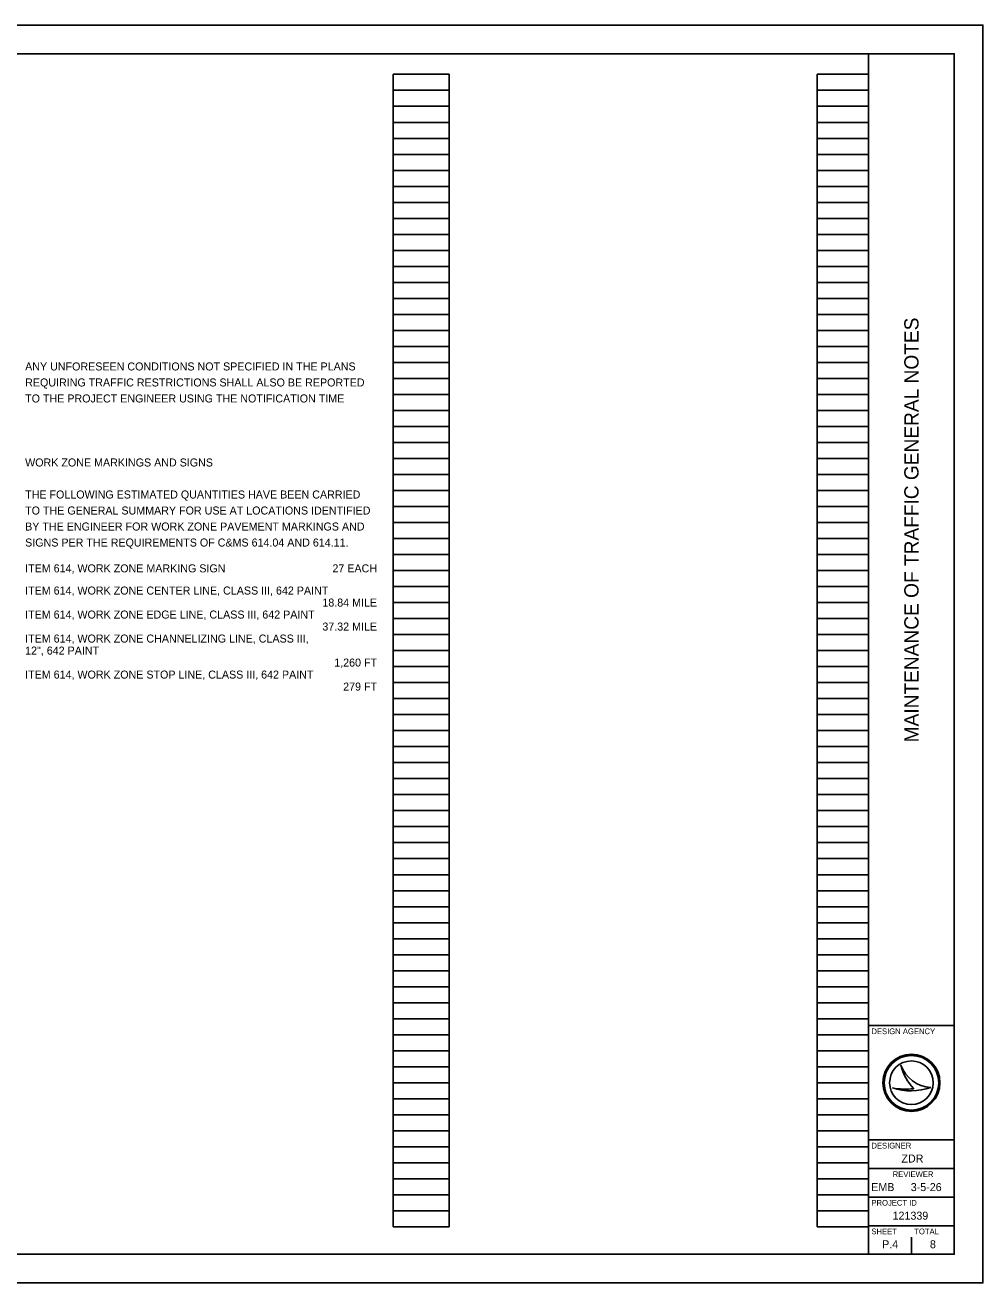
# Model space of a CAD drawing. Extents: x 0 to 34, y 0 to 22.
# Drawn here: x 17.24 to 34, y 0 to 22 of the extents above; entities that cross this region are included whole.
import ezdxf

# ---------------------------------------------------------------- set-up
doc = ezdxf.new("R2010")
doc.units = 0
for name, color, linetype in [('SH_Border', 7, 'Continuous'), ('SH_Cut_Line', 7, 'Continuous'), ('SH_Data', 7, 'Continuous'), ('SH_Text', 7, 'Continuous')]:
    doc.layers.add(name, color=color, linetype=linetype)

msp = doc.modelspace()

# ---------------------------------------------------------------- linework, layer by layer
at = {"layer": 'SH_Border'}
for p, q in [((32, 0.5), (32, 21.5)), ((32, 4.5), (33.5, 4.5)), ((32, 2.5), (33.5, 2.5)), ((32, 2), (33.5, 2)), ((32, 1.5), (33.5, 1.5)), ((32, 1), (33.5, 1))]:
    msp.add_line(p, q, dxfattribs=at)
msp.add_lwpolyline([(1.5, 21.5), (33.5, 21.5), (33.5, 0.5), (1.5, 0.5)], close=True, dxfattribs=at)
at = {"layer": 'SH_Cut_Line'}
msp.add_lwpolyline([(0, 0), (34, 0), (34, 22), (0, 22)], close=True, dxfattribs=at)
at = {"layer": 'SH_Data'}
for p, q in [((23.68, 0.98), (23.68, 21.14)), ((23.68, 21.14), (24.66, 21.14)), ((24.66, 0.98), (24.66, 21.14)), ((31.1, 0.98), (31.1, 21.14)), ((31.1, 21.14), (32, 21.14)), ((32, 0.98), (32, 21.14)), ((23.68, 20.86), (24.66, 20.86)), ((31.1, 20.86), (32, 20.86)), ((23.68, 20.58), (24.66, 20.58)), ((31.1, 20.58), (32, 20.58)), ((23.68, 20.3), (24.66, 20.3)), ((31.1, 20.3), (32, 20.3)), ((23.68, 20.02), (24.66, 20.02)), ((31.1, 20.02), (32, 20.02)), ((23.68, 19.74), (24.66, 19.74)), ((31.1, 19.74), (32, 19.74)), ((23.68, 19.46), (24.66, 19.46)), ((31.1, 19.46), (32, 19.46)), ((23.68, 19.18), (24.66, 19.18)), ((31.1, 19.18), (32, 19.18)), ((23.68, 18.9), (24.66, 18.9)), ((31.1, 18.9), (32, 18.9)), ((23.68, 18.62), (24.66, 18.62)), ((31.1, 18.62), (32, 18.62)), ((23.68, 18.34), (24.66, 18.34)), ((31.1, 18.34), (32, 18.34)), ((23.68, 18.06), (24.66, 18.06)), ((31.1, 18.06), (32, 18.06)), ((23.68, 17.78), (24.66, 17.78)), ((31.1, 17.78), (32, 17.78)), ((23.68, 17.5), (24.66, 17.5)), ((31.1, 17.5), (32, 17.5)), ((23.68, 17.22), (24.66, 17.22)), ((31.1, 17.22), (32, 17.22)), ((23.68, 16.94), (24.66, 16.94)), ((31.1, 16.94), (32, 16.94)), ((23.68, 16.66), (24.66, 16.66)), ((31.1, 16.66), (32, 16.66)), ((23.68, 16.38), (24.66, 16.38)), ((31.1, 16.38), (32, 16.38)), ((23.68, 16.1), (24.66, 16.1)), ((31.1, 16.1), (32, 16.1)), ((23.68, 15.82), (24.66, 15.82)), ((31.1, 15.82), (32, 15.82)), ((23.68, 15.54), (24.66, 15.54)), ((31.1, 15.54), (32, 15.54)), ((23.68, 15.26), (24.66, 15.26)), ((31.1, 15.26), (32, 15.26)), ((23.68, 14.98), (24.66, 14.98)), ((31.1, 14.98), (32, 14.98)), ((23.68, 14.7), (24.66, 14.7)), ((31.1, 14.7), (32, 14.7)), ((23.68, 14.42), (24.66, 14.42)), ((31.1, 14.42), (32, 14.42)), ((23.68, 14.14), (24.66, 14.14)), ((31.1, 14.14), (32, 14.14)), ((23.68, 13.86), (24.66, 13.86)), ((31.1, 13.86), (32, 13.86)), ((23.68, 13.58), (24.66, 13.58)), ((31.1, 13.58), (32, 13.58)), ((23.68, 13.3), (24.66, 13.3)), ((31.1, 13.3), (32, 13.3)), ((23.68, 13.02), (24.66, 13.02)), ((31.1, 13.02), (32, 13.02)), ((23.68, 12.74), (24.66, 12.74)), ((31.1, 12.74), (32, 12.74)), ((23.68, 12.46), (24.66, 12.46)), ((31.1, 12.46), (32, 12.46)), ((23.68, 12.18), (24.66, 12.18)), ((31.1, 12.18), (32, 12.18)), ((23.68, 11.9), (24.66, 11.9)), ((31.1, 11.9), (32, 11.9)), ((23.68, 11.62), (24.66, 11.62)), ((31.1, 11.62), (32, 11.62)), ((23.68, 11.34), (24.66, 11.34)), ((31.1, 11.34), (32, 11.34)), ((23.68, 11.06), (24.66, 11.06)), ((31.1, 11.06), (32, 11.06)), ((23.68, 10.78), (24.66, 10.78)), ((31.1, 10.78), (32, 10.78)), ((23.68, 10.5), (24.66, 10.5)), ((31.1, 10.5), (32, 10.5)), ((23.68, 10.22), (24.66, 10.22)), ((31.1, 10.22), (32, 10.22)), ((23.68, 9.94), (24.66, 9.94)), ((31.1, 9.94), (32, 9.94)), ((23.68, 9.66), (24.66, 9.66)), ((31.1, 9.66), (32, 9.66)), ((23.68, 9.38), (24.66, 9.38)), ((31.1, 9.38), (32, 9.38)), ((23.68, 9.1), (24.66, 9.1)), ((31.1, 9.1), (32, 9.1)), ((23.68, 8.82), (24.66, 8.82)), ((31.1, 8.82), (32, 8.82)), ((23.68, 8.54), (24.66, 8.54)), ((31.1, 8.54), (32, 8.54)), ((23.68, 8.26), (24.66, 8.26)), ((31.1, 8.26), (32, 8.26)), ((23.68, 7.98), (24.66, 7.98)), ((31.1, 7.98), (32, 7.98)), ((23.68, 7.7), (24.66, 7.7)), ((31.1, 7.7), (32, 7.7)), ((23.68, 7.42), (24.66, 7.42)), ((31.1, 7.42), (32, 7.42)), ((23.68, 7.14), (24.66, 7.14)), ((31.1, 7.14), (32, 7.14)), ((23.68, 6.86), (24.66, 6.86)), ((31.1, 6.86), (32, 6.86)), ((23.68, 6.58), (24.66, 6.58)), ((31.1, 6.58), (32, 6.58)), ((23.68, 6.3), (24.66, 6.3)), ((31.1, 6.3), (32, 6.3)), ((23.68, 6.02), (24.66, 6.02)), ((31.1, 6.02), (32, 6.02)), ((23.68, 5.74), (24.66, 5.74)), ((31.1, 5.74), (32, 5.74)), ((23.68, 5.46), (24.66, 5.46)), ((31.1, 5.46), (32, 5.46)), ((23.68, 5.18), (24.66, 5.18)), ((31.1, 5.18), (32, 5.18)), ((23.68, 4.9), (24.66, 4.9)), ((31.1, 4.9), (32, 4.9)), ((23.68, 4.62), (24.66, 4.62)), ((31.1, 4.62), (32, 4.62)), ((23.68, 4.34), (24.66, 4.34)), ((31.1, 4.34), (32, 4.34)), ((23.68, 4.06), (24.66, 4.06)), ((31.1, 4.06), (32, 4.06)), ((23.68, 3.78), (24.66, 3.78)), ((31.1, 3.78), (32, 3.78)), ((32.567, 3.81), (32.567, 3.81)), ((23.68, 3.5), (24.66, 3.5)), ((31.1, 3.5), (32, 3.5)), ((32.417, 3.41), (32.417, 3.41)), ((32.75, 3.5), (32.75, 3.5)), ((33.087, 3.419), (33.087, 3.419)), ((23.68, 3.22), (24.66, 3.22)), ((31.1, 3.22), (32, 3.22)), ((23.68, 2.94), (24.66, 2.94)), ((31.1, 2.94), (32, 2.94)), ((23.68, 2.66), (24.66, 2.66)), ((31.1, 2.66), (32, 2.66)), ((23.68, 2.38), (24.66, 2.38)), ((31.1, 2.38), (32, 2.38)), ((23.68, 2.1), (24.66, 2.1)), ((31.1, 2.1), (32, 2.1)), ((23.68, 1.82), (24.66, 1.82)), ((31.1, 1.82), (32, 1.82)), ((23.68, 1.54), (24.66, 1.54)), ((31.1, 1.54), (32, 1.54)), ((23.68, 1.26), (24.66, 1.26)), ((31.1, 1.26), (32, 1.26)), ((23.68, 0.98), (24.66, 0.98)), ((31.1, 0.98), (32, 0.98)), ((32.375, 0.675), (32.375, 0.675)), ((32.75, 0.5), (32.75, 0.8))]:
    msp.add_line(p, q, dxfattribs=at)
for radius in [0.5, 0.477, 0.477, 0.382]:
    msp.add_circle((32.75, 3.5), radius, dxfattribs=at)
for centre, radius, start, end in [((33.116, 3.998), 0.58, 198.9257, 198.9319), ((33.347, 3.97), 0.796, 191.6379, 191.6421), ((33.116, 3.998), 0.58, 198.9319, 267.1657), ((33.347, 3.97), 0.796, 191.6421, 226.0947), ((32.739, 4.37), 1.013, 251.4576, 290.0832), ((32.648, 4.654), 1.266, 259.4964, 259.4995), ((32.739, 4.37), 1.013, 251.4527, 251.4576), ((32.648, 4.654), 1.266, 259.4995, 276.6672)]:
    msp.add_arc(centre, radius, start, end, dxfattribs=at)

# ---------------------------------------------------------------- texts
msp.add_text('MAINTENANCE OF TRAFFIC GENERAL NOTES', height=0.25, rotation=90, dxfattribs=at).set_placement((32.875, 9.455))
for s, height, p in [('DESIGN AGENCY', 0.1, (32.05, 4.35)), ('DESIGNER', 0.1, (32.05, 2.35)), ('ZDR', 0.14, (32.575, 2.105)), ('REVIEWER', 0.1, (32.422, 1.85)), ('EMB', 0.14, (32.047, 1.605)), ('3-5-26', 0.14, (32.738, 1.605)), ('PROJECT ID', 0.1, (32.05, 1.35)), ('121339', 0.14, (32.42, 1.105)), ('SHEET', 0.1, (32.05, 0.85)), ('TOTAL', 0.1, (32.8, 0.85)), ('P.4', 0.14, (32.237, 0.605)), ('8', 0.14, (33.074, 0.605))]:
    msp.add_text(s, height=height, dxfattribs=at).set_placement(p)
at = {"layer": 'SH_Text'}
for s, p in [('ANY UNFORESEEN CONDITIONS NOT SPECIFIED IN THE PLANS', (17.24, 15.96)), ('REQUIRING TRAFFIC RESTRICTIONS SHALL ALSO BE REPORTED', (17.24, 15.68)), ('TO THE PROJECT ENGINEER USING THE NOTIFICATION TIME', (17.24, 15.4)), ('WORK ZONE MARKINGS AND SIGNS', (17.24, 14.28)), ('THE FOLLOWING ESTIMATED QUANTITIES HAVE BEEN CARRIED', (17.24, 13.72)), ('TO THE GENERAL SUMMARY FOR USE AT LOCATIONS IDENTIFIED', (17.24, 13.44)), ('BY THE ENGINEER FOR WORK ZONE PAVEMENT MARKINGS AND', (17.24, 13.16)), ('SIGNS PER THE REQUIREMENTS OF C&MS 614.04 AND 614.11.', (17.24, 12.88)), ('ITEM 614, WORK ZONE MARKING SIGN                                    27 EACH', (17.24, 12.428)), ('ITEM 614, WORK ZONE CENTER LINE, CLASS III, 642 PAINT', (17.24, 12.04)), ('                                                                                                    18.84 MILE', (17.24, 11.83)), ('ITEM 614, WORK ZONE EDGE LINE, CLASS III, 642 PAINT', (17.24, 11.62)), ('                                                                                                    37.32 MILE', (17.24, 11.41)), ('ITEM 614, WORK ZONE CHANNELIZING LINE, CLASS III, ', (17.24, 11.2)), ('12", 642 PAINT', (17.24, 10.99)), ('                                                                                                        1,260 FT', (17.24, 10.78)), ('ITEM 614, WORK ZONE STOP LINE, CLASS III, 642 PAINT', (17.24, 10.57)), ('                                                                                                           279 FT                           ', (17.24, 10.36))]:
    msp.add_text(s, height=0.14, dxfattribs=at).set_placement(p)

doc.saveas('drawing.dxf')
